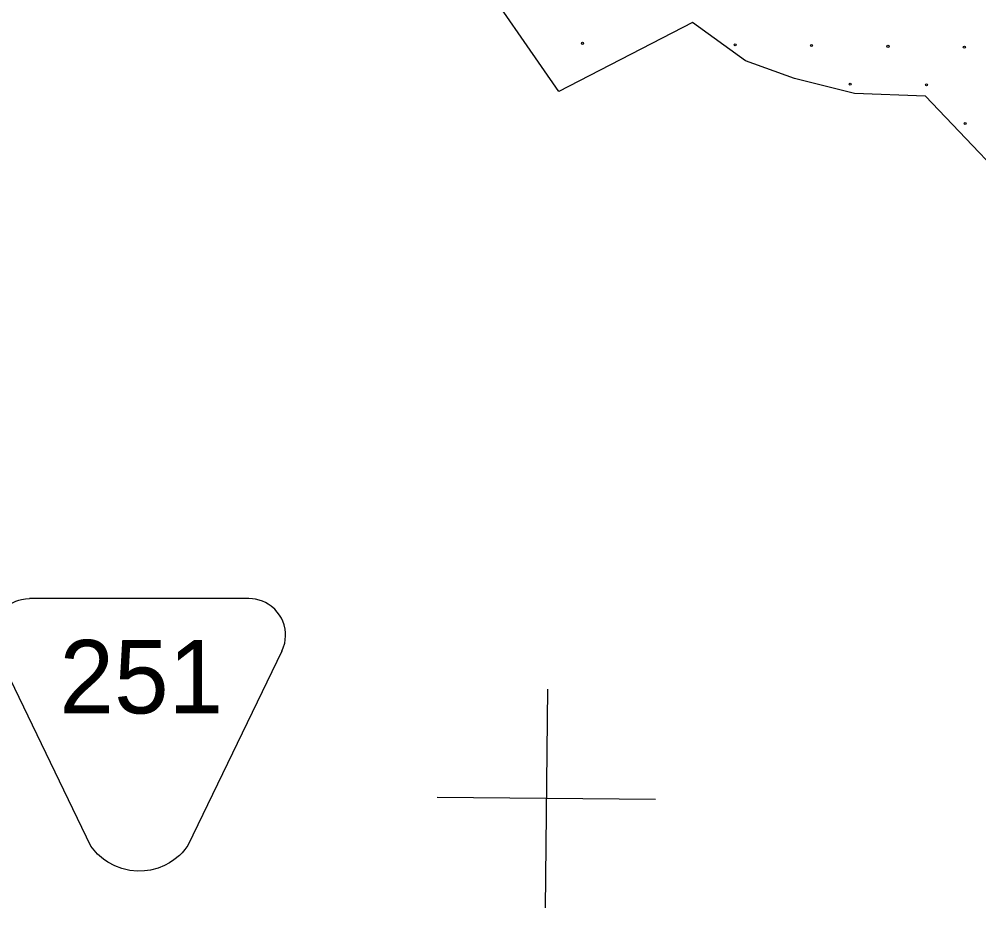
# Model space of a CAD drawing. Extents: x 1612280 to 1883141, y 560852 to 780851.
# Drawn here: x 1694990 to 1699821, y 637732 to 642204 of the extents above; entities that cross this region are included whole.
import ezdxf

# ---------------------------------------------------------------- set-up
doc = ezdxf.new("R2010")
doc.units = 0
for name, color, linetype in [('DESIGN - EROSION CONTROL - Devices', 7, 'Continuous'), ('DESIGN - ROW - Easement Linework and Patterning', 7, 'Continuous'), ('DESIGN - SCRATCH - User 1', 7, 'Continuous'), ('SURVEY - DRAINAGE - Bridge Hydraulic Data - Points - Locators', 7, 'Continuous')]:
    doc.layers.add(name, color=color, linetype=linetype)

msp = doc.modelspace()

# ---------------------------------------------------------------- linework, layer by layer
at = {"layer": 'DESIGN - EROSION CONTROL - Devices'}
for centre in [(1697825.1, 642082.7), (1697825.1, 642082.7), (1698594.2, 642075.2), (1698594.2, 642075.2), (1698978.7, 642071.5), (1698978.7, 642071.5), (1699363.3, 642067.8), (1699363.3, 642067.8), (1699747.8, 642064), (1699747.8, 642064), (1699172.9, 641877.3), (1699172.9, 641877.3), (1699557.4, 641873.6), (1699557.4, 641873.6), (1699751.6, 641679.5), (1699751.6, 641679.5)]:
    msp.add_circle(centre, 5.28, dxfattribs=at)
at = {"layer": 'DESIGN - ROW - Easement Linework and Patterning'}
for points in [[(1695349.5, 638042.7), (1694875, 639023.2), (1694864.5, 639050.2), (1694860, 639068.2), (1694857.4, 639086.1), (1694856.5, 639101.7), (1694857.2, 639119.5), (1694859.4, 639136), (1694865.1, 639159.2), (1694871.6, 639176.8), (1694879.5, 639192.9), (1694889.5, 639209), (1694899.8, 639222.6), (1694915.3, 639238.8), (1694929.5, 639250.8), (1694942.7, 639260), (1694955.5, 639267.3), (1694972, 639275), (1694987.6, 639280.5), (1695000.4, 639283.9), (1695022, 639287.5), (1695041.3, 639288.5)], [(1695349.5, 638042.7), (1694875, 639023.2), (1694864.5, 639050.2), (1694860, 639068.2), (1694857.4, 639086.1), (1694856.5, 639101.7), (1694857.2, 639119.5), (1694859.4, 639136), (1694865.1, 639159.2), (1694871.6, 639176.8), (1694879.5, 639192.9), (1694889.5, 639209), (1694899.8, 639222.6), (1694915.3, 639238.8), (1694929.5, 639250.8), (1694942.7, 639260), (1694955.5, 639267.3), (1694972, 639275), (1694987.6, 639280.5), (1695000.4, 639283.9), (1695022, 639287.5), (1695041.3, 639288.5)], [(1696312, 639023.2), (1696318.2, 639040.9), (1696326.2, 639064), (1696329.1, 639080.7), (1696330.5, 639101.1), (1696330.1, 639116.4), (1696328, 639134.3), (1696322.7, 639156.7), (1696316.2, 639174.9), (1696309.4, 639189.4), (1696300.7, 639204.3), (1696289.1, 639220.3), (1696276.5, 639234.2), (1696257.8, 639250.6), (1696242.9, 639260.9), (1696229, 639268.6), (1696214.7, 639275.1), (1696198.4, 639280.8), (1696178.7, 639285.5), (1696164.8, 639287.5), (1696145.7, 639288.5), (1695041.3, 639288.5)], [(1696312, 639023.2), (1696318.2, 639040.9), (1696326.2, 639064), (1696329.1, 639080.7), (1696330.5, 639101.1), (1696330.1, 639116.4), (1696328, 639134.3), (1696322.7, 639156.7), (1696316.2, 639174.9), (1696309.4, 639189.4), (1696300.7, 639204.3), (1696289.1, 639220.3), (1696276.5, 639234.2), (1696257.8, 639250.6), (1696242.9, 639260.9), (1696229, 639268.6), (1696214.7, 639275.1), (1696198.4, 639280.8), (1696178.7, 639285.5), (1696164.8, 639287.5), (1696145.7, 639288.5), (1695041.3, 639288.5)], [(1696312, 639023.2), (1695839, 638045.6), (1695823.8, 638025.3), (1695809.4, 638008.9), (1695796.1, 637995.8), (1695768, 637972.8), (1695745.9, 637958.2), (1695721.9, 637945.4), (1695689.1, 637932), (1695651.4, 637921.9), (1695619.7, 637917.3), (1695584.7, 637916.3), (1695547.3, 637919.7), (1695506.9, 637928.9), (1695471, 637942.4), (1695435.5, 637961.3), (1695413.5, 637976.4), (1695384.1, 638001.9), (1695349.5, 638042.7)], [(1696312, 639023.2), (1695839, 638045.6), (1695823.8, 638025.3), (1695809.4, 638008.9), (1695796.1, 637995.8), (1695768, 637972.8), (1695745.9, 637958.2), (1695721.9, 637945.4), (1695689.1, 637932), (1695651.4, 637921.9), (1695619.7, 637917.3), (1695584.7, 637916.3), (1695547.3, 637919.7), (1695506.9, 637928.9), (1695471, 637942.4), (1695435.5, 637961.3), (1695413.5, 637976.4), (1695384.1, 638001.9), (1695349.5, 638042.7)]]:
    msp.add_lwpolyline(points, dxfattribs=at)
at = {"layer": 'DESIGN - SCRATCH - User 1'}
for points in [[(1697706.7, 641841), (1697254.1, 642493)], [(1697706.7, 641841), (1697254.1, 642493)], [(1698378.9, 642187.6), (1697706.7, 641841)], [(1698378.9, 642187.6), (1697706.7, 641841)], [(1699551.7, 641817), (1699195.1, 641830.7), (1698893.3, 641906.2), (1698646.4, 641995.5), (1698378.9, 642187.6)], [(1699551.7, 641817), (1699195.1, 641830.7), (1698893.3, 641906.2), (1698646.4, 641995.5), (1698378.9, 642187.6)], [(1701767.1, 639991.4), (1701259.5, 640149.3), (1700978.3, 640334.6), (1700546.2, 640767), (1700127.8, 641213.1), (1699551.7, 641817)], [(1701767.1, 639991.4), (1701259.5, 640149.3), (1700978.3, 640334.6), (1700546.2, 640767), (1700127.8, 641213.1), (1699551.7, 641817)]]:
    msp.add_lwpolyline(points, dxfattribs=at)
at = {"layer": 'SURVEY - DRAINAGE - Bridge Hydraulic Data - Points - Locators'}
for p, q in [((1697648.7, 638831.9), (1697637.9, 637731.9)), ((1697648.7, 638831.9), (1697637.9, 637731.9)), ((1698193.3, 638276.5), (1697093.4, 638287.2)), ((1698193.3, 638276.5), (1697093.4, 638287.2))]:
    msp.add_line(p, q, dxfattribs=at)

# ---------------------------------------------------------------- texts
at = {"layer": 'DESIGN - ROW - Easement Linework and Patterning'}
msp.add_text('251', height=369.61, rotation=0.0012, dxfattribs=at).set_placement((1695192.3, 638710.2))
msp.add_text('251', height=369.61, rotation=0.0012, dxfattribs=at).set_placement((1695192.3, 638710.2))

doc.saveas('drawing.dxf')
